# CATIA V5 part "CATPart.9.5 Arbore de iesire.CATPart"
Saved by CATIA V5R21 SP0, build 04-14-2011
Part number: Arbore de iesire
Bounding box of the stored display mesh (mm): x 0 to 175, y -29.961 to 29.961, z -29.961 to 29.961
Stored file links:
  C:\Users\MIRCEA\Desktop\MOM\Mogan\model\CATPart.9.5 Arbore de iesire.CATPart
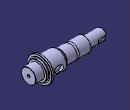
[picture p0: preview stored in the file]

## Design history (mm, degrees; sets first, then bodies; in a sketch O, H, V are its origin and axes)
Parameters
  L1 = 42 mm
  D1 = 25 mm
  X1 = 4 mm
  Lp1 = 21 mm
  h1 = 4 mm
  b1 = 8 mm
  L2 = 0 mm
  D2 = 25 mm
  L3 = 64 mm
  D3 = 35 mm
  L4 = 0 mm
  D4 = 40 mm
  X2 = 15 mm
  Lp2 = 7.392 mm
  b2 = 14 mm
  h2 = 5.5 mm
  L5 = 38 mm
  D5 = 45 mm
  L6 = 5 mm
  D6 = 60 mm
  L7 = 0 mm
  D7 = 50 mm
  L8 = 5 mm
  D8 = 45 mm
  L9 = 21 mm
  D9 = 35 mm
Body1 (main body)
  Sketch1 on xy-plane, origin (0, 0, 0), H (1, 0, 0), V (0, 1, 0)
    line L1 (0, 0) -> (0, 12.5)
    line L2 (0, 12.5) -> (42, 12.5)
    line L3 (42, 12.5) -> (42, 12.5)
    line L4 (106, 20) -> (106, 20)
    line L5 (106, 20) -> (106, 22.5)
    line L6 (106, 22.5) -> (144, 22.5)
    line L7 (144, 22.5) -> (144, 30)
    line L8 (144, 30) -> (149, 30)
    line L9 (149, 30) -> (149, 25)
    line L10 (149, 25) -> (149, 25)
    line L11 (149, 25) -> (149, 22.5)
    line L12 (149, 22.5) -> (154, 22.5)
    axis line L13 (200, 0) -> (0, 0)
    line L14 (42, 12.5) -> (42, 12.5)
    line L15 (42, 12.5) -> (42, 17.5)
    line L16 (42, 17.5) -> (106, 17.5)
    line L17 (106, 17.5) -> (106, 20)
    line L18 (154, 22.5) -> (154, 17.5)
    line L19 (154, 17.5) -> (175, 17.5)
    line L20 (175, 17.5) -> (175, 0)
    point P20 (175, 0)
    distance L1 L3 = 42 {= L1}
    distance L7 L5 = 38 {= L5}
    distance L7 L9 = 5 {= L6}
    distance L11 L9 = 0 {= L7}
    length L14 = 0 {= L2}
    length L16 = 64 {= L3}
    length L4 = 0 {= L4}
    length L1 = 12.5 {= D1/2}
    distance L14 L13 = 12.5 {= D2/2}
    distance L16 L13 = 17.5 {= D3/2}
    distance L4 L13 = 20 {= D4/2}
    distance L6 L13 = 22.5 {= D5/2}
    distance L8 L13 = 30 {= D6/2}
    distance L10 L13 = 25 {= D7/2}
    distance L12 L13 = 22.5 {= D8/2}
    length L12 = 5 {= L8}
    length L19 = 21 {= L9}
    length L20 = 17.5 {= D9/2}
    vertical: L1 V, L3 V, L5 V, L7 V, L9 V, L11 V, L15 V, L17 V, L18 V, L20 V
    horizontal: L2 H, L4 H, L6 H, L8 H, L10 H, L12 H, L13 H, L14 H, L16 H, L19 H
    coincidence: P20 L13
  Shaft1: profile Sketch1, axis edge of Sketch1, angle 360
  Plane1: type Offset, RefPlane zx-plane, Offset 22.5 {= D5/2}
  Sketch2 on Plane1, origin (0, 22.5, 0), H (1, 0, 0), V (0, 0, -1)
    construction line L1 (121, 0) -> (128.392, 0)
    point P1 (121, 0)
    point P2 (128.392, 0)
    line L2 (121, 7) -> (128.392, 7)
    line L3 (128.392, -7) -> (121, -7)
    arc A1 centre (128.392, 0) radius 7 from (128.392, 7) to (128.392, -7) cw
    arc A2 centre (121, 0) radius 7 from (121, -7) to (121, 7) cw
    reference intersected point E1 (106, 0) from face of Shaft1 from Sketch1.L5
    distance L2 L3 = 14 {= b2}
    distance P1 P2 = 7.392 {= Lp2}
    distance E1 P1 = 15 {= X2}
    coincidence: P1 H
    horizontal: L1 H
    tangency: A1 L2, A2 L2, A1 L3, A2 L3
    symmetry: L3 L2 H
  Pocket1 "Canal pana 2": profile Sketch2, direction (0, -1, 0), length 5.5 {= h2}
  Plane2: type Offset, RefPlane zx-plane, Offset 12.5 {= D1/2}
  Sketch3 on Plane2, origin (0, 12.5, 0), H (-1, 0, 0), V (0, 0, 1)
    point P1 (-60.8003, 0)
    point P2 (-5, 0)
    construction line L1 (-17, 0) -> (4, 0)
    point P3 (-17, 0)
    point P4 (4, 0)
    line L2 (-17, 4) -> (4, 4)
    line L3 (4, -4) -> (-17, -4)
    arc A1 centre (4, 0) radius 4 from (4, 4) to (4, -4) cw
    arc A2 centre (-17, 0) radius 4 from (-17, -4) to (-17, 4) cw
    reference intersected point E1 (0, 0) from face of Shaft1 from Sketch1.L1
    distance L2 L3 = 8 {= b1}
    distance P3 P4 = 21 {= Lp1}
    distance E1 P4 = 4 {= X1}
    coincidence: P3 H
    horizontal: L1 H
    tangency: A1 L2, A2 L2, A1 L3, A2 L3
    symmetry: L3 L2 H
  Pocket2 "Canal pana 1": profile Sketch3, direction (0, -1, 0), length 4 {= h1}
  Sketch4 on xy-plane, origin (0, 0, 0), H (1, 0, 0), V (0, 1, 0)
    point P1 (100, 19)
    line L1 (100, 19) -> (100.3595, 17.8052)
    arc A1 centre (99.9881, 17.6934) radius 0.3879 from (100.3595, 17.8052) to (99.8722, 17.3233) cw
    line L2 (99.8722, 17.3233) -> (99.4821, 17.3917)
    arc A2 centre (99.5808, 17.9545) radius 0.5714 from (99.4821, 17.3917) to (99.1603, 17.5677) cw
    distance P1 H = 19
    distance P1 V = 100
    tangency: A1 L1, A2 L2
  Groove1: profile Sketch4, axis axis of face of Shaft1 from Sketch1.L16, angle 360
  Sketch5 on xy-plane, origin (0, 0, 0), H (1, 0, 0), V (0, 1, 0)
    point P1 (73, 22.5)
    point P2 (73, 22.5)
    arc A1 centre (73, 22.5) radius 5.6924 from (69.9424, 17.6985) to (76.0635, 17.7022) ccw
    distance P1 H = 22.5
    distance P1 V = 73
    distance P1 P2 = 0
  Groove2: profile Sketch5, axis axis of face of Shaft1 from Sketch1.L6, angle 360
  Sketch6 on face of Shaft1 from Sketch1.L1, origin (0, 0, 0), H (0, 1, 0), V (0, 0, -1)
    point P1 (0, 0)
  Hole1: placed by Sketch6, at (0, 0, 0) direction (1, 0, 0), diameter 5, depth 5, V-bottom angle 60, countersink depth 2, countersink angle 50
  Chamfer1: length 0.5, angle 45, on edge [face of Shaft1 from Sketch1.L2 | face of Shaft1 from Sketch1.L1]; edge [face of Shaft1 from Sketch1.L16 | face of Shaft1 from Sketch1.L15]; edge [face of Shaft1 from Sketch1.L6 | face of Shaft1 from Sketch1.L5]; edge [face of Shaft1 from Sketch1.L8 | face of Shaft1 from Sketch1.L7]; face of Shaft1 from Sketch1.L8
  Chamfer2: length 0.5, angle 45, on edge [face of Shaft1 from Sketch1.L20 | face of Shaft1 from Sketch1.L19]; edge [face of Shaft1 from Sketch1.L18 | face of Shaft1 from Sketch1.L12]
  Sketch7 on face of Shaft1 from Sketch1.L20, origin (175, 0, 0), H (0, 1, 0), V (0, 0, 1)
    point P1 (0, 0)
    coincidence: P1 O
  DatumSurface1
  Sketch8 on face of Shaft1 from Sketch1.L20, origin (175, 0, 0), H (0, 1, 0), V (0, 0, 1)
    point P1 (0, 0)
    reference projected point E1 (0, 0) from Sketch7.P1
    coincidence: E1 P1
  Hole2: placed by Sketch8, at (175, 0, 0) direction (-1, 0, 0), diameter 5, depth 5, V-bottom angle 60, countersink depth 2, countersink angle 50
Relations
  Sketch1.distance(L7 L5) = L5 (deactivated)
